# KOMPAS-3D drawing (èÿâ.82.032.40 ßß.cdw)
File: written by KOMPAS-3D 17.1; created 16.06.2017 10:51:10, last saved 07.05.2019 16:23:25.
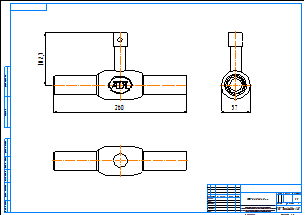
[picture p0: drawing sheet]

Sheet 1: A2, landscape

Title block, sheet 1: name: КШГ.82.032.40 сс; material: Внимание! Данный продукт является объектом авторского права ООО «Торговый Дом АДЛ». / Запрещается изменение, копирование, распространение / (в том числе путем копирования на другие сайты и ресурсы в Интернете) / или любое иное использование информации и объектов без предварительного / согласия правообладателя (ООО «Торговый Дом АДЛ»).; scale: 1:1; sheets: 1; organisation: ООО "Торговый дом АДЛ"; sheet format: A2; stored path: C:\Users\tra\Desktop\2д чертежи\Шаровые краны БИВАЛ\КШ_Бивал_серия_82_85\KOMPAS 2D\КШГ.82.032.40 сс.cdw

Views: Спереди 1, Проекционный вид 2, Проекционный вид 3
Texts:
  Klimkovich
  ADL
Dimensions and other numbers on the sheet: 260; 102,7; 57; 1:1; 1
